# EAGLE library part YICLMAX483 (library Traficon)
MAX 3483 3.3V powered, 10Mbps ans Slew-Rate-Limited True RS485 transceiver
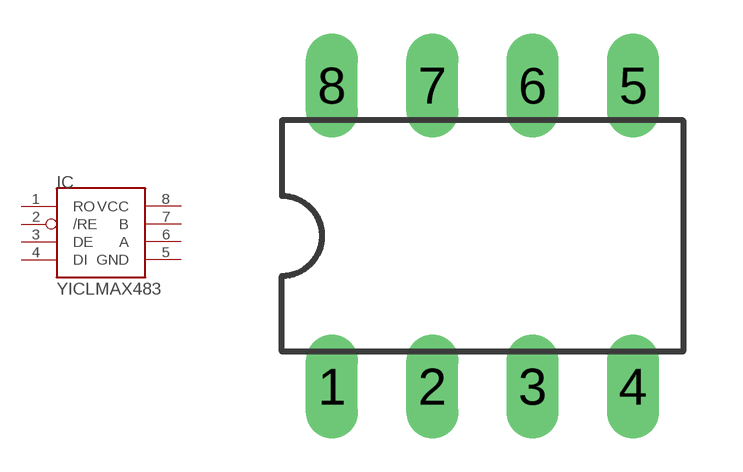
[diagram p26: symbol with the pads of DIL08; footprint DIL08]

Designator prefix IC

## YICLMAX483  [DIL08]
1  RO  out
2  /RE  in
3  DE  in
4  DI  in
5  GND  pas
6  A
7  B
8  VCC  pas

## Footprint DIL08 (pad centres in mm)
Dual In Line Package
drill 0.813 long: 1 -3.81,-3.81; 2 -1.27,-3.81; 3 1.27,-3.81; 4 3.81,-3.81; 5 3.81,3.81; 6 1.27,3.81; 7 -1.27,3.81; 8 -3.81,3.81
